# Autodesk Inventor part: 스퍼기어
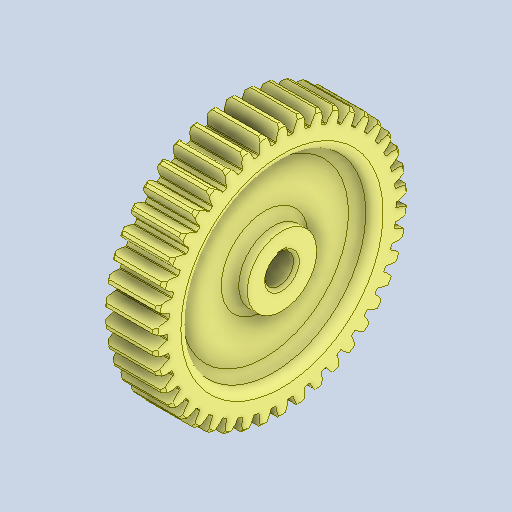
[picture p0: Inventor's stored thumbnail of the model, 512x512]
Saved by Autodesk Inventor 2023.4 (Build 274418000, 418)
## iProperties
Created: 2024-09
Part Number: 스퍼기어
Material: 강철, 탄소
Document SubType Name: Modeling
Designer: EDU
Density: 7.85 g/cm^3
Appearance: 기본값
Author: jhkim
Sending System: Autodesk Inventor 2025
Preprocessor: ST-DEVELOPER v20
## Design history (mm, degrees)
feature "솔리드1"
node "솔리드2"
